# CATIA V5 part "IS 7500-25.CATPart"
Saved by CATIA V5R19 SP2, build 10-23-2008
Part number: IS 7500-25
Bounding box of the stored display mesh (mm): x -74.81 to 74.81, y -74.81 to 74.81, z 0 to 205
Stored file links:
  C:\Users\Bora\Desktop\3D Katı model\IS serisi\IS 7500\IS 7500-25.CATPart
  C:\Program Files\Dassault Systemes\B19\intel_a\reffiles\standard\MetricThickPitch.txt
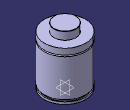
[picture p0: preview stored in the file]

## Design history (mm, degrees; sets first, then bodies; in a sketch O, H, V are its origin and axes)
Body1 (main body)
  Sketch1 on yz-plane, origin (0, 0, 0), H (0, 1, 0), V (0, 0, 1)
    point P1 (75, 155)
    point P2 (75, 150)
    point P5 (40, 204)
    point P7 (40, 204)
    point P12 (75, 150)
    point P13 (75, 155)
    arc A1 centre (75, 152.5) radius 2.5 from (75, 155) to (75, 150) ccw
    line L1 (75, 0) -> (75, 8)
    line L2 (40, 204) -> (40, 177)
    arc A2 centre (39, 204) radius 1 from (40, 204) to (39, 205) ccw
    line L3 (71, 15) -> (71, 8)
    line L4 (75, 15) -> (75, 150)
    line L5 (75, 155) -> (75, 177)
    line L6 (39, 205) -> (0, 205)
    point P15 (0, 205)
    line L7 (40, 177) -> (75, 177)
    line L8 (0, 0) -> (75, 0)
    line L9 (71, 15) -> (75, 15)
    line L10 (71, 8) -> (75, 8)
    coincidence: P15 V, P1 P13, P2 P12, P5 P7
    tangency: L6 A2
    horizontal: L7 H, L8 H, L9 H, L10 H
  Shaft1: profile Sketch1, axis Sketch1.V, angle 360
  Sketch2 on face of Shaft1 from Sketch1.L8, origin (0, 0, 0), H (1, 0, 0), V (0, -1, 0)
    point P1 (50, 0)
    distance P1 V = 50
  Hole1: placed by Sketch2, at (50, 0, 0) direction (0, 0, 1), diameter 8.376, depth 16, threaded "M10", thread diameter 10, thread depth 16, pitch 1.5
  CircPattern1: of Hole1, instances 4, angular step 90, axis from xy-plane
